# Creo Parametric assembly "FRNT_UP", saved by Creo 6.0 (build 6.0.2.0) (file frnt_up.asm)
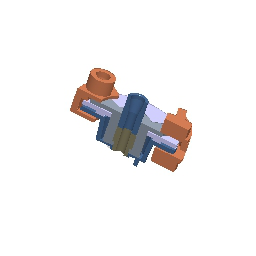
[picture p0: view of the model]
Units: Inch lbm Second (Pro/E Default); INCH, POUND, SECS

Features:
  1. coordinate system "DEFAULT"
  2. datum plane "ADTM4"
  3. datum plane "ADTM5"
  4. datum plane "ADTM6"
  5. component "H1"
  6. component "H11_12"
  7. component "J2_4"
  8. component "C4"
  9. datum plane "ADTM3"
  10. component "K44"
  11. component "K42"
  12. component "BEARING"
  13. coordinate system "ACS0"

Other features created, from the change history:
  planar section "XSEC0001" (3 times)
  planar section "B"
  planar section "C"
